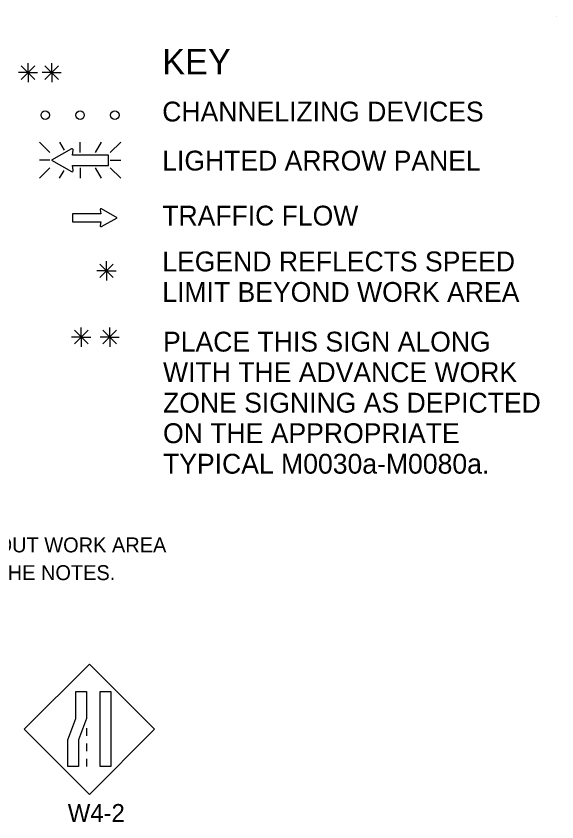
# Model space of a CAD drawing. Extents: x 16576 to 19508, y 5728 to 6974.
# Drawn here: x 18197.1 to 18450.5, y 6553 to 6930.8 of the extents above; entities that cross this region are included whole.
import ezdxf

# ---------------------------------------------------------------- set-up
doc = ezdxf.new("R2010")
doc.units = 0
for name, color, linetype in [('BORDER', 7, 'Continuous'), ('MT_SCRATCH_LEVEL_E', 7, 'Continuous'), ('TRAFFIC_SIGNS_PR', 7, 'Continuous'), ('TYPICAL_TEXT_DIMEN_EX', 7, 'Continuous'), ('TYPICAL_TEXT_DIMEN_PR', 7, 'Continuous')]:
    doc.layers.add(name, color=color, linetype=linetype)

msp = doc.modelspace()

# ---------------------------------------------------------------- linework, layer by layer
at = {"layer": 'BORDER'}
msp.add_line((18450.55, 6930.8), (18450.55, 6930.8), dxfattribs=at)
at = {"layer": 'MT_SCRATCH_LEVEL_E'}
for p, q in [((18236.44, 6839.92), (18236.75, 6838.14)), ((18244.36, 6836.29), (18237.12, 6840.4)), ((18236.75, 6838.14), (18223.5, 6838.14)), ((18223.5, 6838.14), (18223.5, 6834.4)), ((18237.12, 6832.15), (18244.36, 6836.29)), ((18223.5, 6834.4), (18236.75, 6834.4)), ((18236.75, 6834.4), (18236.44, 6832.62))]:
    msp.add_line(p, q, dxfattribs=at)
for centre, start, end in [((18236.9, 6839.99), 60.4248, 189.9638), ((18236.9, 6832.55), 170.0362, 299.7731)]:
    msp.add_arc(centre, 0.463, start, end, dxfattribs=at)
at = {"layer": 'TRAFFIC_SIGNS_PR'}
for p, q in [((18207.95, 6871.72), (18212.88, 6866.79)), ((18219.71, 6867.9), (18217.5, 6871.72)), ((18227.03, 6866.79), (18227.03, 6871.72)), ((18234.26, 6866.79), (18237.11, 6871.72)), ((18241.18, 6866.79), (18246.11, 6871.72)), ((18212.88, 6863.23), (18207.95, 6863.23)), ((18241.18, 6863.23), (18246.11, 6863.23)), ((18207.95, 6854.74), (18212.88, 6859.68)), ((18217.46, 6854.74), (18219.57, 6858.4)), ((18227.03, 6859.68), (18227.03, 6854.74)), ((18237.16, 6854.74), (18234.31, 6859.68)), ((18241.18, 6859.68), (18246.11, 6854.74)), ((18231.46, 6626.95), (18200.91, 6596.4)), ((18262, 6596.4), (18231.46, 6626.95)), ((18230.05, 6596.95), (18230.05, 6593.35)), ((18200.91, 6596.4), (18231.46, 6565.85)), ((18231.46, 6565.85), (18262, 6596.4)), ((18230.05, 6589.75), (18230.05, 6586.15)), ((18230.05, 6582.55), (18230.05, 6578.95))]:
    msp.add_line(p, q, dxfattribs=at)
for points in [[(18222.96, 6868.51), (18213.67, 6863.23), (18222.96, 6857.91)], [(18223.83, 6858.54), (18223.43, 6860.81), (18240.44, 6860.81), (18240.44, 6865.61), (18223.43, 6865.61), (18223.83, 6867.89)]]:
    msp.add_lwpolyline(points, dxfattribs=at)
for points in [[(18230.05, 6614.1), (18230.05, 6601.52), (18226.29, 6591.53), (18226.29, 6578.95), (18221.24, 6578.95), (18221.24, 6591.53), (18225, 6601.52), (18225, 6614.1)], [(18241.46, 6614.1), (18241.46, 6578.95), (18236.4, 6578.95), (18236.4, 6614.1)]]:
    msp.add_lwpolyline(points, close=True, dxfattribs=at)
for centre in [(18210.74, 6884.34), (18227.04, 6884.34), (18243.34, 6884.34)]:
    msp.add_circle(centre, 2, dxfattribs=at)
for centre, radius, start, end in [((18223.25, 6867.98), 0.598, 350.7308, 118.8916), ((18223.24, 6858.43), 0.597, 241.4833, 9.9593)]:
    msp.add_arc(centre, radius, start, end, dxfattribs=at)
at = {"layer": 'TYPICAL_TEXT_DIMEN_EX'}
for p, q in [((18236.25, 6814.55), (18242.62, 6808.17)), ((18242.62, 6814.55), (18236.25, 6808.17)), ((18239.43, 6811.36), (18239.43, 6815.82)), ((18239.43, 6811.36), (18234.9, 6811.36)), ((18239.43, 6811.36), (18242.62, 6811.36)), ((18239.43, 6811.36), (18243.91, 6811.36)), ((18239.43, 6811.36), (18239.43, 6806.86)), ((18224.42, 6783.48), (18230.8, 6777.11)), ((18230.8, 6783.48), (18224.42, 6777.11)), ((18227.61, 6780.3), (18227.61, 6784.75)), ((18237.74, 6783.48), (18244.12, 6777.11)), ((18244.12, 6783.48), (18237.74, 6777.11)), ((18240.93, 6780.3), (18240.93, 6784.75)), ((18227.61, 6780.3), (18223.08, 6780.3)), ((18227.61, 6780.3), (18230.8, 6780.3)), ((18227.61, 6780.3), (18232.08, 6780.3)), ((18227.61, 6780.3), (18227.61, 6775.8)), ((18240.93, 6780.3), (18236.4, 6780.3)), ((18240.93, 6780.3), (18244.12, 6780.3)), ((18240.93, 6780.3), (18245.41, 6780.3)), ((18240.93, 6780.3), (18240.93, 6775.8))]:
    msp.add_line(p, q, dxfattribs=at)
at = {"layer": 'TYPICAL_TEXT_DIMEN_PR'}
for p, q in [((18199.47, 6907.53), (18205.84, 6901.15)), ((18205.84, 6907.53), (18199.47, 6901.15)), ((18202.65, 6904.34), (18202.65, 6908.8)), ((18216.97, 6907.53), (18210.59, 6901.15)), ((18210.6, 6907.53), (18216.97, 6901.15)), ((18213.78, 6904.34), (18213.78, 6908.8)), ((18202.65, 6904.34), (18198.12, 6904.34)), ((18202.65, 6904.34), (18205.84, 6904.34)), ((18202.65, 6904.34), (18207.13, 6904.34)), ((18202.65, 6904.34), (18202.65, 6899.84)), ((18213.78, 6904.34), (18209.25, 6904.34)), ((18213.78, 6904.34), (18216.97, 6904.34)), ((18213.78, 6904.34), (18218.26, 6904.34)), ((18213.78, 6904.34), (18213.78, 6899.84))]:
    msp.add_line(p, q, dxfattribs=at)

# ---------------------------------------------------------------- texts
at = {"layer": 'TRAFFIC_SIGNS_PR'}
for s, height, p in [('PLACE THROUGHOUT WORK AREA', 7, (18107.3, 6679.35)), ('AS INDICATED IN THE NOTES.', 7, (18107.3, 6666.35)), ('W4-2', 8.37, (18221.28, 6552.98))]:
    msp.add_text(s, height=height, dxfattribs=at).set_placement(p)
at = {"layer": 'TYPICAL_TEXT_DIMEN_EX'}
for s, height, p in [('KEY', 12, (18265.58, 6903.45)), ('CHANNELIZING DEVICES', 9.3, (18265.58, 6881.4)), ('LIGHTED ARROW PANEL', 9.3, (18265.58, 6858.4)), ('TRAFFIC FLOW', 9.3, (18265.58, 6832.61)), ('LEGEND REFLECTS SPEED', 9.31, (18265.58, 6811.11)), ('LIMIT BEYOND WORK AREA', 9.31, (18265.58, 6796.8)), ('PLACE THIS SIGN ALONG', 9.31, (18265.93, 6773.5)), ('WITH THE ADVANCE WORK', 9.31, (18265.93, 6759.19)), ('ZONE SIGNING AS DEPICTED', 9.31, (18265.93, 6744.88)), ('ON THE APPROPRIATE', 9.31, (18265.93, 6730.57)), ('TYPICAL M0030a-M0080a.', 9.31, (18265.93, 6716.26))]:
    msp.add_text(s, height=height, dxfattribs=at).set_placement(p)

doc.saveas('drawing.dxf')
